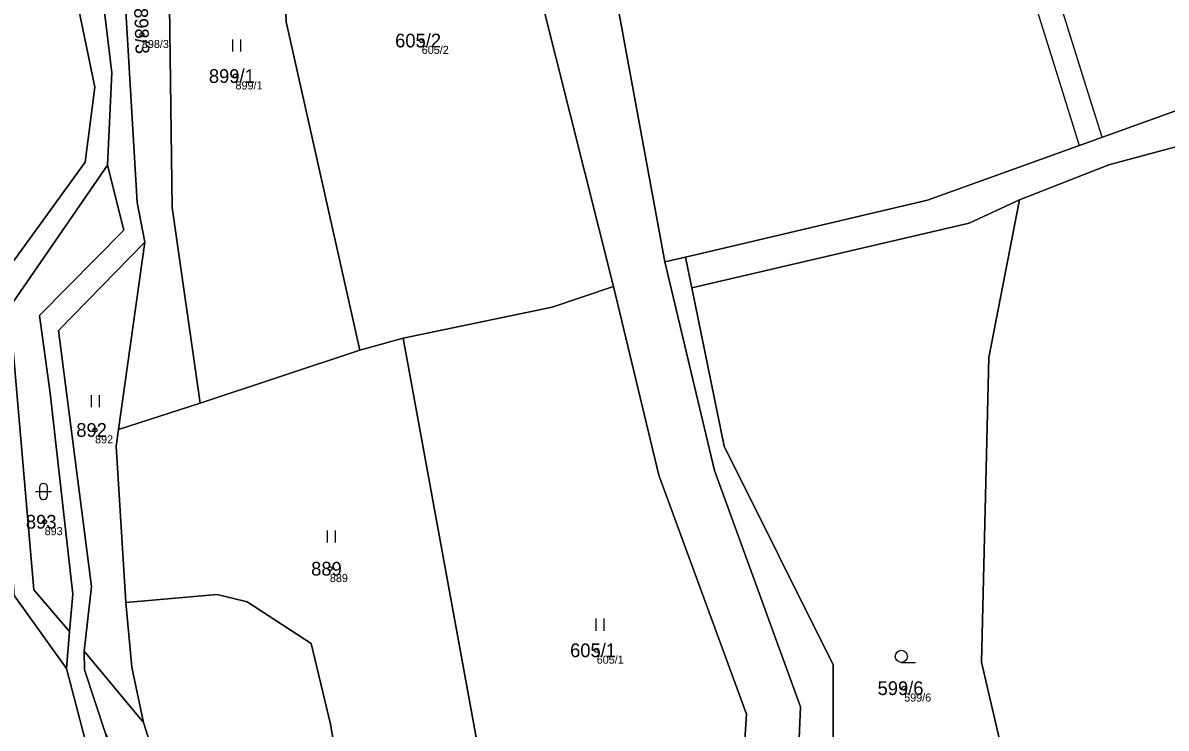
# Model space of a CAD drawing. Extents: x -554500 to -548272, y -1079733 to -1073730.
# Drawn here: x -553605.4 to -553463.7, y -1076317.6 to -1076230.3 of the extents above; entities that cross this region are included whole.
import ezdxf

# ---------------------------------------------------------------- set-up
doc = ezdxf.new("R2010")
doc.units = 0
for name, color, linetype in [('Definiční body', 7, 'Continuous'), ('Hranice parcel', 7, 'Continuous'), ('Parcelní čísla', 7, 'Continuous'), ('Polygon parcely', 7, 'Continuous'), ('Věcná břemena k části', 7, 'Continuous'), ('Značky kultur', 7, 'Continuous')]:
    doc.layers.add(name, color=color, linetype=linetype)

msp = doc.modelspace()

# ---------------------------------------------------------------- linework, layer by layer
at = {"layer": 'Definiční body'}
for centre in [(-553590.64, -1076231.71994), (-553555.96, -1076232.44994), (-553579.04, -1076236.84994), (-553596.44, -1076280.67994), (-553602.69, -1076292.04994), (-553567.34, -1076297.85994), (-553534.28, -1076307.96994), (-553496.18, -1076312.65994)]:
    msp.add_circle(centre, 0.25, dxfattribs=at)
at = {"layer": 'Hranice parcel'}
for p, q in [((-553593.54, -1076280.6), (-553590.29, -1076257.41)), ((-553525.82, -1076259.86), (-553523.26, -1076259.26)), ((-553523.26, -1076259.26), (-553522.48, -1076263.07)), ((-553558.27, -1076269.3), (-553563.63, -1076270.79)), ((-553547.63, -1076327.3), (-553558.27, -1076269.3)), ((-553563.63, -1076270.79), (-553583.41, -1076277.34)), ((-553583.41, -1076277.34), (-553593.54, -1076280.6)), ((-553599.97, -1076310.24), (-553599.59, -1076305.64)), ((-553597.79, -1076308.06), (-553590.42, -1076316.92)), ((-553594.32, -1076331.86), (-553599.97, -1076310.24)), ((-553582.47, -1076342.18), (-553590.42, -1076316.92))]:
    msp.add_line(p, q, dxfattribs=at)
for points in [[(-553540.03, -1076062.78), (-553538.46, -1076191.18), (-553525.82, -1076259.86)], [(-553192.34, -1076153.61), (-553234.53, -1076172.39), (-553265.17, -1076184.53), (-553306.2, -1076199.03), (-553341.51, -1076209.72), (-553370.28, -1076220.81), (-553470.81, -1076247.85), (-553481.88, -1076252.19)], [(-553545.07, -1076195.19), (-553541.12, -1076227.45), (-553532.22, -1076262.89)], [(-553590.29, -1076257.41), (-553591.22, -1076252.51), (-553593.52, -1076213.47), (-553589.17, -1076196.82)], [(-553587.62, -1076196.97), (-553586.88, -1076253.14), (-553583.41, -1076277.34)], [(-553563.63, -1076270.79), (-553572.76, -1076230.14), (-553573.9, -1076198.27)], [(-553625.27, -1076259.04), (-553618.89, -1076261.76), (-553608.07, -1076261.88), (-553597.66, -1076247.5), (-553596.46, -1076238.22), (-553600.32, -1076219.6), (-553598.84, -1076214.52), (-553597.02, -1076214.51)], [(-553594.88, -1076247.87), (-553594.36, -1076236.43), (-553597.02, -1076214.51)], [(-553523.26, -1076259.26), (-553493.27, -1076252.2), (-553447.72, -1076235.81), (-553416.52, -1076228.3)], [(-553594.88, -1076247.87), (-553607.04, -1076265.5), (-553604.04, -1076300.47), (-553599.59, -1076305.64)], [(-553599.59, -1076305.64), (-553599.2, -1076301.03), (-553602, -1076276.12), (-553603.33, -1076266.52), (-553592.87, -1076255.93), (-553594.88, -1076247.87)], [(-553522.48, -1076263.07), (-553488.13, -1076255.08), (-553481.88, -1076252.19)], [(-553481.88, -1076252.19), (-553485.71, -1076271.7), (-553486.59, -1076309.43), (-553480, -1076337.85), (-553474.64, -1076350.25), (-553465.35, -1076351.76)], [(-553590.29, -1076257.41), (-553600.96, -1076268.37), (-553596.88, -1076300.05), (-553597.79, -1076308.06)], [(-553525.82, -1076259.86), (-553519.67, -1076285.69), (-553509.02, -1076314.96), (-553509.93, -1076336.3), (-553510.73, -1076345.52), (-553506.82, -1076358.3), (-553504.05, -1076362.31)], [(-553532.22, -1076262.89), (-553539.78, -1076265.45), (-553558.27, -1076269.3)], [(-553532.22, -1076262.89), (-553526.59, -1076286.28), (-553515.73, -1076315.86), (-553517.78, -1076348.04)], [(-553522.48, -1076263.07), (-553518.48, -1076282.68), (-553504.97, -1076309.76), (-553504.93, -1076342.23), (-553500.25, -1076348.23), (-553499.89, -1076353.5), (-553497.12, -1076357.51), (-553504.05, -1076362.31)], [(-553593.54, -1076280.6), (-553593.83, -1076282.69), (-553592.64, -1076302.06)], [(-553599.97, -1076310.24), (-553606.45, -1076301.17), (-553607.1, -1076292.7)], [(-553592.64, -1076302.06), (-553581.33, -1076301.05), (-553577.6, -1076301.98), (-553569.67, -1076307.11), (-553567.28, -1076317.12), (-553565.03, -1076330.28), (-553547.63, -1076327.3)], [(-553590.42, -1076316.92), (-553591.88, -1076310.05), (-553592.64, -1076302.06)], [(-553597.79, -1076308.06), (-553597.74, -1076310.37), (-553595.13, -1076318.29)]]:
    msp.add_lwpolyline(points, dxfattribs=at)
at = {"layer": 'Polygon parcely'}
for points in [[(-553558.75, -1075962.49), (-553556.64, -1075979.11), (-553552.27, -1076012.92), (-553551.24, -1076028.23), (-553549.31, -1076041.25), (-553545.99, -1076080.74), (-553545.66, -1076118.89), (-553548.04, -1076162.34), (-553545.07, -1076195.19), (-553541.12, -1076227.45), (-553532.22, -1076262.89), (-553526.59, -1076286.28), (-553515.73, -1076315.86), (-553517.78, -1076348.04), (-553513.1, -1076368.85), (-553513, -1076369.32), (-553505.39, -1076372.56), (-553496.78, -1076380.19), (-553489.13, -1076396.51), (-553486.95, -1076405.57), (-553481.77, -1076427.04)], [(-553473.83, -1076425.13), (-553486.73, -1076383.91), (-553488.43, -1076380.02), (-553496.6, -1076372.46), (-553500.07, -1076369.25), (-553504.05, -1076362.31), (-553506.82, -1076358.3), (-553510.73, -1076345.52), (-553509.93, -1076336.3), (-553509.02, -1076314.96), (-553519.67, -1076285.69), (-553525.82, -1076259.86), (-553538.46, -1076191.18), (-553540.03, -1076062.78), (-553540.38, -1076037.29), (-553540.45, -1076028.75), (-553545.66, -1076016.64), (-553546.66, -1076010.11), (-553546.79, -1076009.24), (-553546.2, -1075996.04), (-553549.26, -1075995.93), (-553549.97, -1075979.57), (-553550.13, -1075975.63)], [(-553261.77, -1076176.99), (-553328.38, -1076201.9), (-553345.23, -1076206.92), (-553355.43, -1076210.16), (-553373.61, -1076218.02), (-553389.24, -1076221.89), (-553406.03, -1076225.78), (-553416.52, -1076228.3), (-553447.72, -1076235.81), (-553493.27, -1076252.2), (-553523.26, -1076259.26), (-553522.48, -1076263.07), (-553488.13, -1076255.08), (-553481.88, -1076252.19), (-553470.81, -1076247.85), (-553370.28, -1076220.81), (-553341.51, -1076209.72), (-553306.2, -1076199.03), (-553265.17, -1076184.53)], [(-553265.17, -1076184.53), (-553306.2, -1076199.03), (-553341.51, -1076209.72), (-553370.28, -1076220.81), (-553470.81, -1076247.85), (-553481.88, -1076252.19), (-553485.71, -1076271.7), (-553486.59, -1076309.43), (-553480, -1076337.85), (-553474.64, -1076350.25), (-553465.35, -1076351.76), (-553452.78, -1076349.7), (-553453.97, -1076345.27), (-553442.81, -1076342.26), (-553442.35, -1076343.97), (-553440.02, -1076341.73), (-553429.08, -1076342.46), (-553400.83, -1076331.52), (-553313.75, -1076308.26), (-553295.84, -1076305.09), (-553270.78, -1076295.45)], [(-553556.89, -1076419.64), (-553568.06, -1076396.16), (-553588.53, -1076369.27), (-553592.55, -1076353.54), (-553591.16, -1076331.78), (-553595.13, -1076318.29), (-553597.74, -1076310.37), (-553597.79, -1076308.06), (-553596.88, -1076300.05), (-553600.96, -1076268.37), (-553590.29, -1076257.41), (-553591.22, -1076252.51), (-553593.52, -1076213.47)], [(-553597.02, -1076214.51), (-553594.36, -1076236.43), (-553594.88, -1076247.87), (-553592.87, -1076255.93), (-553603.33, -1076266.52), (-553602, -1076276.12), (-553599.2, -1076301.03), (-553599.59, -1076305.64), (-553599.97, -1076310.24), (-553594.32, -1076331.86), (-553594.67, -1076341.34), (-553595.25, -1076352.23), (-553592.96, -1076369.36), (-553578.84, -1076388.07), (-553571.37, -1076398.14), (-553566.59, -1076408.35), (-553560.05, -1076420.35)]]:
    msp.add_lwpolyline(points, dxfattribs=at)
for points in [[(-553447.72, -1076235.81), (-553416.52, -1076228.3), (-553506.31, -1076103.2), (-553523.83, -1076076.58), (-553528.4, -1076064.05), (-553540.03, -1076062.78), (-553538.46, -1076191.18), (-553525.82, -1076259.86), (-553523.26, -1076259.26), (-553493.27, -1076252.2)], [(-553596.46, -1076238.22), (-553600.32, -1076219.6), (-553598.84, -1076214.52), (-553597.02, -1076214.51), (-553591.89, -1076197.54), (-553594.34, -1076176.78), (-553595.76, -1076157.97), (-553599.82, -1076160.12), (-553616.67, -1076177.59), (-553628.58, -1076182.47), (-553637.33, -1076182.08), (-553638.71, -1076191.84), (-553637.11, -1076198.62), (-553636.1, -1076214.83), (-553632.8, -1076245.42), (-553625.87, -1076255.86), (-553625.27, -1076259.04), (-553618.89, -1076261.76), (-553608.07, -1076261.88), (-553597.66, -1076247.5)], [(-553545.07, -1076195.19), (-553573.9, -1076198.27), (-553572.76, -1076230.14), (-553563.63, -1076270.79), (-553558.27, -1076269.3), (-553539.78, -1076265.45), (-553532.22, -1076262.89), (-553541.12, -1076227.45)], [(-553593.54, -1076280.6), (-553583.41, -1076277.34), (-553586.88, -1076253.14), (-553587.62, -1076196.97), (-553589.17, -1076196.82), (-553593.52, -1076213.47), (-553591.22, -1076252.51), (-553590.29, -1076257.41)], [(-553573.9, -1076198.27), (-553587.62, -1076196.97), (-553586.88, -1076253.14), (-553583.41, -1076277.34), (-553563.63, -1076270.79), (-553572.76, -1076230.14)], [(-553594.88, -1076247.87), (-553594.36, -1076236.43), (-553597.02, -1076214.51), (-553598.84, -1076214.52), (-553600.32, -1076219.6), (-553596.46, -1076238.22), (-553597.66, -1076247.5), (-553608.07, -1076261.88), (-553618.89, -1076261.76), (-553625.27, -1076259.04), (-553623.74, -1076266.86), (-553617.65, -1076266.44), (-553610.23, -1076265.93), (-553607.39, -1076289.7), (-553607.1, -1076292.7), (-553606.45, -1076301.17), (-553599.97, -1076310.24), (-553599.59, -1076305.64), (-553604.04, -1076300.47), (-553607.04, -1076265.5)], [(-553603.33, -1076266.52), (-553592.87, -1076255.93), (-553594.88, -1076247.87), (-553607.04, -1076265.5), (-553604.04, -1076300.47), (-553599.59, -1076305.64), (-553599.2, -1076301.03), (-553602, -1076276.12)], [(-553497.12, -1076357.51), (-553504.05, -1076362.31), (-553500.07, -1076369.25), (-553490.98, -1076366.84), (-553486.01, -1076360.56), (-553467.04, -1076355.87), (-553465.35, -1076351.76), (-553474.64, -1076350.25), (-553480, -1076337.85), (-553486.59, -1076309.43), (-553485.71, -1076271.7), (-553481.88, -1076252.19), (-553488.13, -1076255.08), (-553522.48, -1076263.07), (-553518.48, -1076282.68), (-553504.97, -1076309.76), (-553504.93, -1076342.23), (-553500.25, -1076348.23), (-553499.89, -1076353.5)], [(-553590.29, -1076257.41), (-553600.96, -1076268.37), (-553596.88, -1076300.05), (-553597.79, -1076308.06), (-553590.42, -1076316.92), (-553591.88, -1076310.05), (-553592.64, -1076302.06), (-553593.83, -1076282.69), (-553593.54, -1076280.6)], [(-553519.67, -1076285.69), (-553509.02, -1076314.96), (-553509.93, -1076336.3), (-553510.73, -1076345.52), (-553506.82, -1076358.3), (-553504.05, -1076362.31), (-553497.12, -1076357.51), (-553499.89, -1076353.5), (-553500.25, -1076348.23), (-553504.93, -1076342.23), (-553504.97, -1076309.76), (-553518.48, -1076282.68), (-553522.48, -1076263.07), (-553523.26, -1076259.26), (-553525.82, -1076259.86)], [(-553545.92, -1076339.22), (-553545.6, -1076340.69), (-553535.33, -1076338.48), (-553532.97, -1076349.27), (-553531.48, -1076348.95), (-553531.26, -1076349.97), (-553527.14, -1076350.06), (-553517.78, -1076348.04), (-553515.73, -1076315.86), (-553526.59, -1076286.28), (-553532.22, -1076262.89), (-553539.78, -1076265.45), (-553558.27, -1076269.3), (-553547.63, -1076327.3)], [(-553608.5, -1076321.95), (-553608.14, -1076324.71), (-553594.32, -1076331.86), (-553599.97, -1076310.24), (-553606.45, -1076301.17), (-553607.1, -1076292.7), (-553617.65, -1076266.44), (-553623.74, -1076266.86)], [(-553547.63, -1076327.3), (-553558.27, -1076269.3), (-553563.63, -1076270.79), (-553583.41, -1076277.34), (-553593.54, -1076280.6), (-553593.83, -1076282.69), (-553592.64, -1076302.06), (-553581.33, -1076301.05), (-553577.6, -1076301.98), (-553569.67, -1076307.11), (-553567.28, -1076317.12), (-553565.03, -1076330.28)], [(-553545.92, -1076339.22), (-553547.63, -1076327.3), (-553565.03, -1076330.28), (-553567.28, -1076317.12), (-553569.67, -1076307.11), (-553577.6, -1076301.98), (-553581.33, -1076301.05), (-553592.64, -1076302.06), (-553591.88, -1076310.05), (-553590.42, -1076316.92), (-553582.47, -1076342.18), (-553580.17, -1076341.37), (-553572.53, -1076357.81), (-553557.28, -1076354.52), (-553554.99, -1076354.02), (-553550.45, -1076353.04), (-553547.61, -1076352.43), (-553550.29, -1076340.16)], [(-553553.97, -1076375.56), (-553554.06, -1076371.73), (-553559.63, -1076372.88), (-553562.73, -1076373.47), (-553569.61, -1076374.76), (-553574.52, -1076376.8), (-553582.47, -1076342.18), (-553590.42, -1076316.92), (-553597.79, -1076308.06), (-553597.74, -1076310.37), (-553595.13, -1076318.29), (-553588.89, -1076330.66), (-553585.37, -1076343.09), (-553579.3, -1076372.59), (-553577.44, -1076377.74), (-553574.19, -1076380.21), (-553568.38, -1076379.43), (-553561.89, -1076378.5), (-553553.5, -1076376.44)]]:
    msp.add_lwpolyline(points, close=True, dxfattribs=at)
at = {"layer": 'Věcná břemena k části'}
msp.add_lwpolyline([(-553474.48, -1076245.44), (-553471.65, -1076244.42), (-553473.87, -1076237.36), (-553495.7, -1076167.5), (-553517.98, -1076096.61), (-553517.63, -1076086), (-553520.49, -1076081.65), (-553521, -1076097.03), (-553498.56, -1076168.4), (-553476.73, -1076238.26)], close=True, dxfattribs=at)
at = {"layer": 'Značky kultur'}
for p, q in [((-553579.361, -1076233.82), (-553579.361, -1076232.32)), ((-553578.36, -1076233.82), (-553578.36, -1076232.32)), ((-553596.891, -1076277.87), (-553596.891, -1076276.37)), ((-553595.89, -1076277.87), (-553595.89, -1076276.37)), ((-553603.331, -1076287.791), (-553603.331, -1076288.792)), ((-553602.329, -1076288.792), (-553602.329, -1076287.791)), ((-553603.831, -1076288.291), (-553601.829, -1076288.291)), ((-553567.641, -1076294.61), (-553567.641, -1076293.11)), ((-553566.64, -1076294.61), (-553566.64, -1076293.11)), ((-553534.341, -1076305.54), (-553534.341, -1076304.04)), ((-553533.34, -1076305.54), (-553533.34, -1076304.04)), ((-553496.533, -1076309.47), (-553494.783, -1076309.47))]:
    msp.add_line(p, q, dxfattribs=at)
msp.add_circle((-553496.53286, -1076308.71981), 0.75, dxfattribs=at)
for centre, start, end in [((-553602.83, -1076287.7909), 0, 180), ((-553602.83, -1076288.7909), 180, 359.9878861)]:
    msp.add_arc(centre, 0.5, start, end, dxfattribs=at)

# ---------------------------------------------------------------- texts
at = {"layer": 'Definiční body'}
for s, p in [('898/3', (-553590.64, -1076233.376)), ('605/2', (-553555.96, -1076234.106)), ('899/1', (-553579.04, -1076238.506)), ('892', (-553596.44, -1076282.336)), ('893', (-553602.69, -1076293.706)), ('889', (-553567.34, -1076299.516)), ('605/1', (-553534.28, -1076309.626)), ('599/6', (-553496.18, -1076314.316))]:
    msp.add_text(s, height=0.999996, dxfattribs=at).set_placement(p)
at = {"layer": 'Parcelní čísla'}
msp.add_text('898/3', height=1.699998, rotation=272, dxfattribs=at).set_placement((-553591.604, -1076228.453))
for s, p in [('605/2', (-553559.258, -1076233.3)), ('899/1', (-553582.338, -1076237.7)), ('892', (-553598.765, -1076281.53)), ('893', (-553605.015, -1076292.9)), ('889', (-553569.665, -1076298.71)), ('605/1', (-553537.578, -1076308.82)), ('599/6', (-553499.478, -1076313.51))]:
    msp.add_text(s, height=1.699998, dxfattribs=at).set_placement(p)

doc.saveas('drawing.dxf')
